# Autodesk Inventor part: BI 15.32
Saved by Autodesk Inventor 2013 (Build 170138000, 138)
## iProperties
Created: 2012-12
Part Number: BI 15.32
Material: Générique
Document SubType Name: Modeling
Designer: jost thierry
Density: 1 g/cm^3
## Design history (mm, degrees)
node "BI 15.321"
node "BI 15.32"
node "Base1"
